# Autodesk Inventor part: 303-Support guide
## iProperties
Author: Philippe
Created: 2001-12
Part Number: 303-Support guide
Material: Par défaut
Document SubType Name: Modélisation
Designer: Philippe
Control State: 0
Master: False
Checked Out: False
PropertySet Name: Design Tracking Control
Shininess: 20.0
Angle Display Precision: 2
Document Length Units: 11269
Document Angle Units: 11283
Document Time Units: 11279
Document Mass Units: 11290
Document Length Units Precision: 3
Document Angle Units Precision: 2
Compacted: False
PropertySet Name: _Private Model Information
Density: 0.0
Volumn: 0.0
Area: 0.0
PropertySet Name: Model Information
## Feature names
1. Extrusion1
2. Perçage1 [Hole]
3. Perçage2 [Hole]
4. Perçage3 [Hole]
